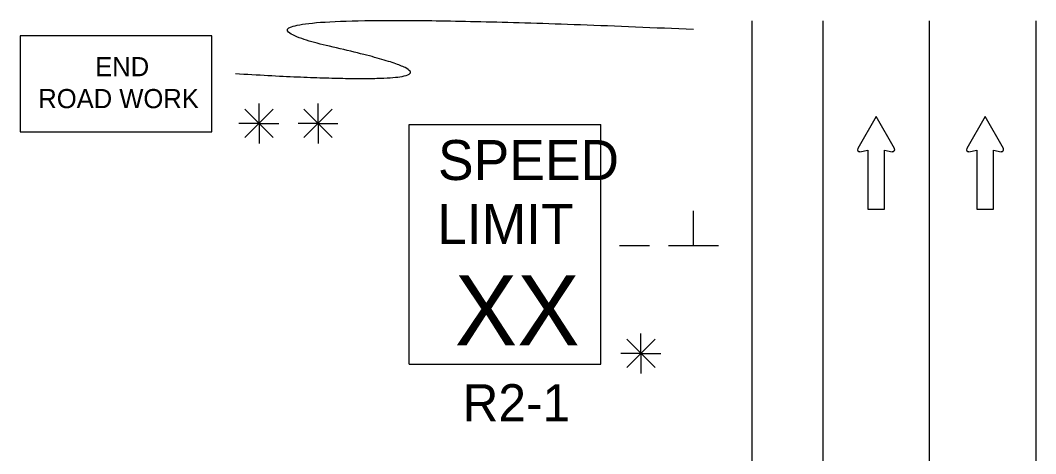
# Model space of a CAD drawing. Extents: x 16576 to 19508, y 5728 to 6974.
# Drawn here: x 17780.8 to 18009.6, y 6823.8 to 6921.4 of the extents above; entities that cross this region are included whole.
import ezdxf

# ---------------------------------------------------------------- set-up
doc = ezdxf.new("R2010")
doc.units = 0
for name, color, linetype in [('ALI_LEGAL_EX', 7, 'Continuous'), ('MT_SCRATCH_LEVEL_E', 7, 'Continuous'), ('PAVT_EDGE_EX', 7, 'Continuous'), ('TRAFFIC_SIGNS_PR', 7, 'Continuous'), ('TYPICAL_TEXT_DIMEN_PR', 7, 'Continuous')]:
    doc.layers.add(name, color=color, linetype=linetype)

msp = doc.modelspace()

# ---------------------------------------------------------------- linework, layer by layer
at = {"layer": 'ALI_LEGAL_EX'}
for p, q in [((17985.63, 6921.33), (17985.63, 6077.19)), ((18009.63, 6921.33), (18009.63, 6077.19))]:
    msp.add_line(p, q, dxfattribs=at)
for points in [[(17985.63, 6921.33), (17985.63, 6896.33)], [(18009.63, 6921.33), (18009.63, 6896.33)]]:
    msp.add_lwpolyline(points, dxfattribs=at)
at = {"layer": 'MT_SCRATCH_LEVEL_E'}
for p, q in [((17973.65, 6899.76), (17969.54, 6892.52)), ((17977.8, 6892.52), (17973.65, 6899.76)), ((17998.21, 6899.76), (17994.1, 6892.52)), ((18002.35, 6892.52), (17998.21, 6899.76)), ((17970.02, 6891.84), (17971.8, 6892.15)), ((17971.8, 6892.15), (17971.8, 6878.9)), ((17975.54, 6878.9), (17975.54, 6892.15)), ((17975.54, 6892.15), (17977.32, 6891.84)), ((17994.58, 6891.84), (17996.35, 6892.15)), ((17996.35, 6892.15), (17996.35, 6878.9)), ((18000.1, 6878.9), (18000.1, 6892.15)), ((18000.1, 6892.15), (18001.87, 6891.84)), ((17971.8, 6878.9), (17975.54, 6878.9)), ((17996.35, 6878.9), (18000.1, 6878.9))]:
    msp.add_line(p, q, dxfattribs=at)
for centre, start, end in [((17969.94, 6892.3), 150.4248, 279.9638), ((17977.39, 6892.3), 260.0362, 29.7731), ((17994.5, 6892.3), 150.4248, 279.9638), ((18001.94, 6892.3), 260.0362, 29.7731)]:
    msp.add_arc(centre, 0.463, start, end, dxfattribs=at)
at = {"layer": 'PAVT_EDGE_EX'}
for p, q in [((17945.63, 6921.33), (17945.63, 5988.51)), ((17961.63, 6921.33), (17961.63, 5988.51))]:
    msp.add_line(p, q, dxfattribs=at)
at = {"layer": 'TRAFFIC_SIGNS_PR'}
for p, q in [((17868.44, 6897.99), (17911.64, 6897.99)), ((17868.44, 6843.99), (17868.44, 6897.99)), ((17911.64, 6843.99), (17911.64, 6897.99)), ((17868.44, 6843.99), (17911.64, 6843.99))]:
    msp.add_line(p, q, dxfattribs=at)
msp.add_lwpolyline([(17780.8, 6896.31), (17823.99, 6896.31), (17823.99, 6917.91), (17780.8, 6917.91)], close=True, dxfattribs=at)
msp.add_open_spline([(17829.27, 6909.42), (17894.43, 6905.55), (17809.41, 6924.9), (17932.51, 6919.41)], degree=2, dxfattribs=at)
at = {"layer": 'TYPICAL_TEXT_DIMEN_PR'}
for p, q in [((17834.59, 6898.19), (17834.59, 6902.65)), ((17847.91, 6898.19), (17847.91, 6902.65)), ((17831.4, 6901.38), (17837.78, 6895.01)), ((17837.78, 6901.38), (17831.4, 6895.01)), ((17844.72, 6901.38), (17851.1, 6895.01)), ((17851.1, 6901.38), (17844.72, 6895.01)), ((17834.59, 6898.19), (17830.06, 6898.19)), ((17834.59, 6898.19), (17837.78, 6898.19)), ((17834.59, 6898.19), (17839.07, 6898.19)), ((17834.59, 6898.19), (17834.59, 6893.69)), ((17847.91, 6898.19), (17843.38, 6898.19)), ((17847.91, 6898.19), (17851.1, 6898.19)), ((17847.91, 6898.19), (17852.39, 6898.19)), ((17847.91, 6898.19), (17847.91, 6893.69)), ((17932.51, 6870.72), (17932.51, 6878.51)), ((17915.86, 6870.72), (17922.63, 6870.72)), ((17926.88, 6870.72), (17938.13, 6870.72)), ((17917.48, 6849.61), (17923.85, 6843.24)), ((17923.85, 6849.61), (17917.48, 6843.24)), ((17920.67, 6846.42), (17920.67, 6850.88)), ((17920.67, 6846.42), (17916.13, 6846.42)), ((17920.67, 6846.42), (17923.85, 6846.42)), ((17920.67, 6846.42), (17925.14, 6846.42)), ((17920.67, 6846.42), (17920.67, 6841.92))]:
    msp.add_line(p, q, dxfattribs=at)

# ---------------------------------------------------------------- texts
at = {"layer": 'TRAFFIC_SIGNS_PR'}
for s, height, p in [('END', 4.31, (17797.67, 6908.83)), ('ROAD WORK', 4.31, (17784.85, 6901.64)), ('SPEED', 9, (17874.93, 6885.46)), ('LIMIT', 9, (17874.75, 6871.06)), ('XX', 15.785, (17878.7, 6848.22)), ('R2-1', 8.37, (17880.45, 6831.12))]:
    msp.add_text(s, height=height, dxfattribs=at).set_placement(p)

doc.saveas('drawing.dxf')
